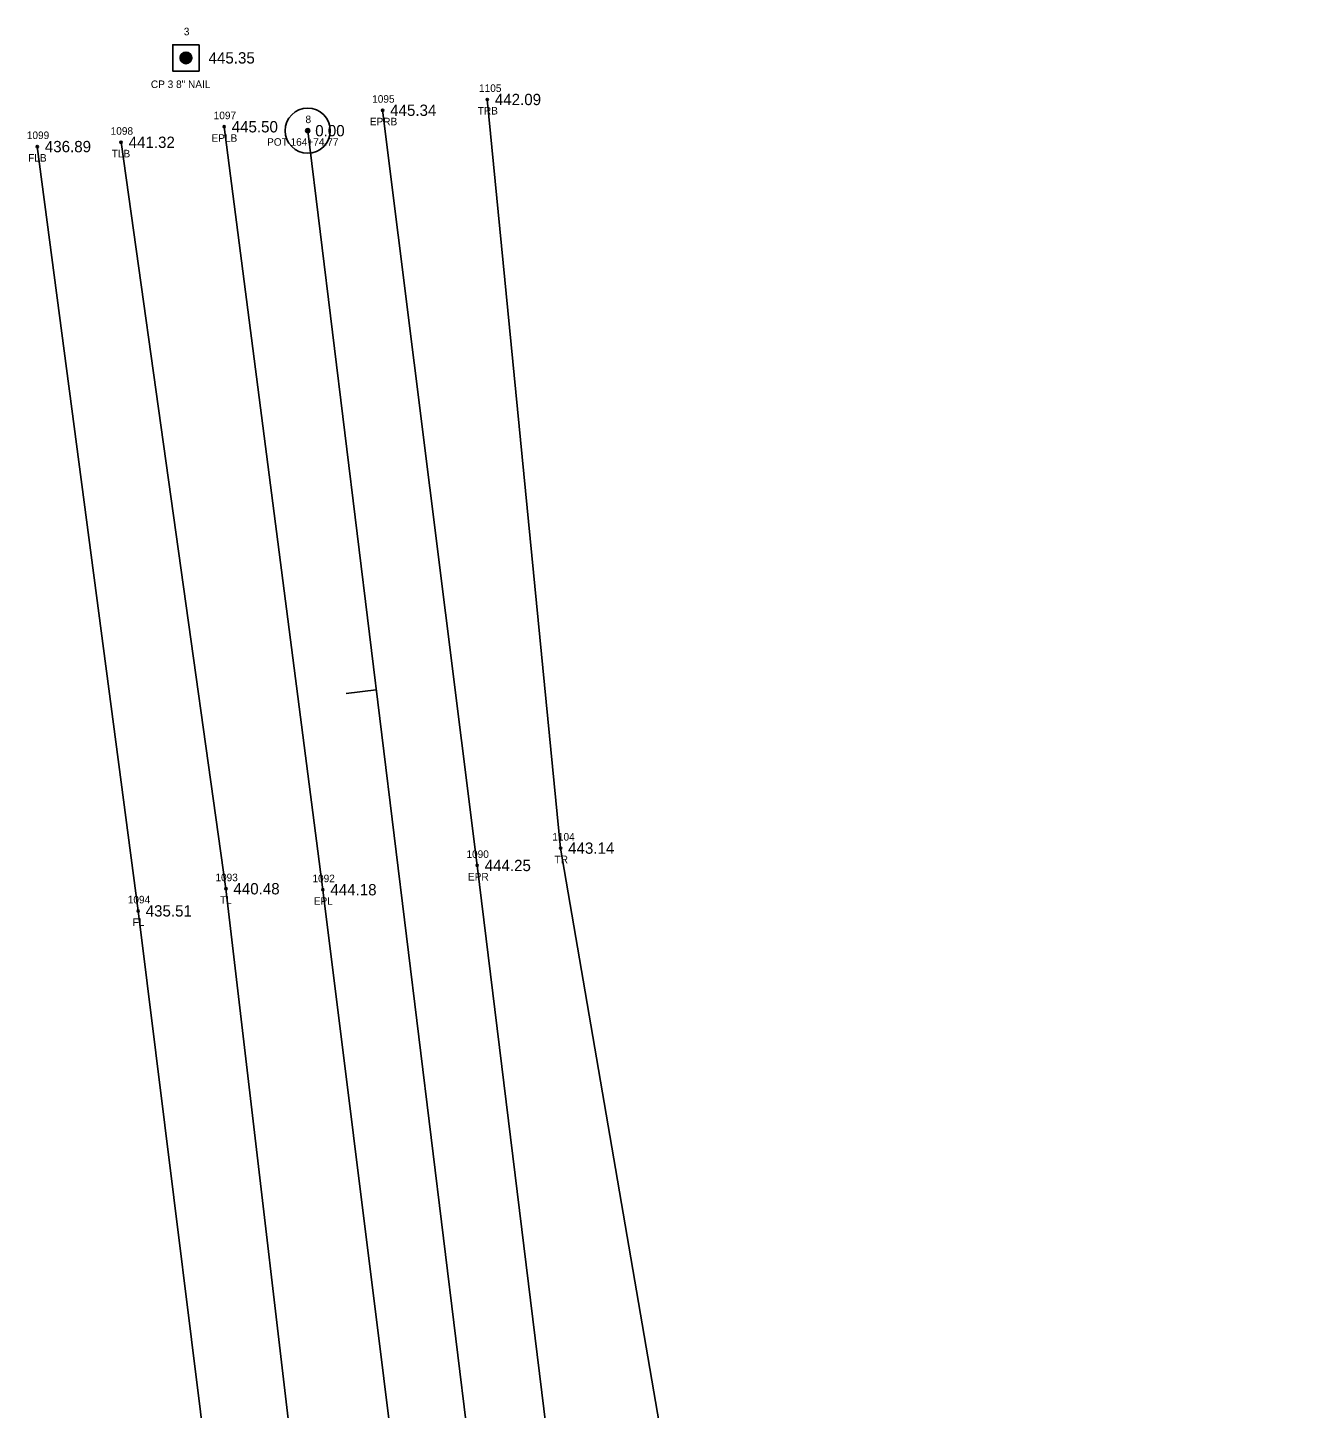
# Model space of a CAD drawing. Extents: x 1858454 to 1858924, y 1147053 to 1148170.
# Drawn here: x 1858580.5 to 1858751.6, y 1147986.7 to 1148169.9 of the extents above; entities that cross this region are included whole.
import ezdxf

# ---------------------------------------------------------------- set-up
doc = ezdxf.new("R2010")
doc.units = 0
for name, color, linetype in [('RD_EX_Fence_Other', 7, 'Continuous'), ('RD_EX_Fence_Other_txCode', 7, 'Continuous'), ('RD_EX_Road', 7, 'Continuous'), ('RD_EX_Road_txCode', 7, 'Continuous'), ('RD_EX_TX_Fence_Other_ELEV', 7, 'Continuous'), ('RD_EX_TX_Road_ELEV', 7, 'Continuous'), ('RD_EX_TX_VEG_ELEV', 7, 'Continuous'), ('RD_EX_VEG', 7, 'Continuous'), ('RD_EX_VEG_txCode', 7, 'Continuous'), ('RD_HC_Cl', 7, 'Continuous'), ('RD_HC_Data', 7, 'Continuous'), ('RD_HC_Data_Tic', 7, 'Continuous'), ('RD_HC_Survey', 7, 'Continuous'), ('RD_HC_Survey_ELEV', 7, 'Continuous'), ('RD_HC_Survey_txCode', 7, 'Continuous'), ('RD_HC_txCode', 7, 'Continuous'), ('RD_SMD_Locator', 7, 'Continuous')]:
    doc.layers.add(name, color=color, linetype=linetype)

msp = doc.modelspace()

# ---------------------------------------------------------------- linework, layer by layer
at = {"layer": 'RD_EX_Fence_Other'}
msp.add_lwpolyline([(1858628.27, 1147625.58), (1858627.01, 1147754.05), (1858615.95, 1147851.08), (1858606.98, 1147957.76), (1858595.17, 1148052.68), (1858581.78, 1148154.12)], dxfattribs=at)
at = {"layer": 'RD_EX_Road'}
for points in [[(1858679.02, 1147660.19), (1858688.73, 1147661.54), (1858677.21, 1147761.6), (1858664.75, 1147860.38), (1858652.33, 1147959.9), (1858640.18, 1148058.71), (1858627.63, 1148158.94)], [(1858679.02, 1147660.19), (1858669.49, 1147658.82), (1858657, 1147758.92), (1858643.96, 1147857.84), (1858631.87, 1147958), (1858619.69, 1148055.49), (1858606.59, 1148156.75)]]:
    msp.add_lwpolyline(points, dxfattribs=at)
at = {"layer": 'RD_EX_VEG'}
for points in [[(1858786.58, 1147073.62), (1858775.98, 1147174.64), (1858762.89, 1147274.03), (1858752.24, 1147373.24), (1858736.96, 1147479.89), (1858729.06, 1147571.9), (1858711.6, 1147670.3), (1858690.41, 1147764.38), (1858680.89, 1147862.43), (1858668.42, 1147961.01), (1858651.26, 1148061.01), (1858641.53, 1148160.37)], [(1858726.29, 1147071.02), (1858708.41, 1147166.41), (1858698.92, 1147264.27), (1858694.52, 1147368.74), (1858682.22, 1147467.57), (1858636.43, 1147636.58), (1858645.41, 1147757.54), (1858631.11, 1147856.08), (1858618.46, 1147956.68), (1858606.82, 1148055.62), (1858592.91, 1148154.69)]]:
    msp.add_lwpolyline(points, dxfattribs=at)
at = {"layer": 'RD_HC_Cl'}
msp.add_line((1858750.25, 1147074.55), (1858617.68, 1148156.23), dxfattribs=at)
at = {"layer": 'RD_HC_Data'}
for radius in [3, 0.282]:
    msp.add_circle((1858617.68, 1148156.23), radius, dxfattribs=at)
at = {"layer": 'RD_HC_Data_Tic'}
msp.add_line((1858626.77, 1148082.01), (1858622.8, 1148081.53), dxfattribs=at)
at = {"layer": 'RD_HC_Survey'}
for p, q in [((1858600.77, 1148165.71), (1858600.77, 1148166.07)), ((1858600.79, 1148165.63), (1858600.79, 1148166.15)), ((1858600.82, 1148165.57), (1858600.82, 1148166.21)), ((1858600.84, 1148165.52), (1858600.84, 1148166.26)), ((1858600.87, 1148165.48), (1858600.87, 1148166.3)), ((1858600.89, 1148165.44), (1858600.89, 1148166.34)), ((1858600.92, 1148165.41), (1858600.92, 1148166.37)), ((1858600.94, 1148165.38), (1858600.94, 1148166.4)), ((1858600.97, 1148165.35), (1858600.97, 1148166.43)), ((1858600.99, 1148165.33), (1858600.99, 1148166.45)), ((1858601.02, 1148165.31), (1858601.02, 1148166.48)), ((1858601.04, 1148165.29), (1858601.04, 1148166.5)), ((1858601.07, 1148165.27), (1858601.07, 1148166.52)), ((1858601.09, 1148165.25), (1858601.09, 1148166.53)), ((1858601.12, 1148165.24), (1858601.12, 1148166.55)), ((1858601.14, 1148165.22), (1858601.14, 1148166.56)), ((1858601.17, 1148165.21), (1858601.17, 1148166.58)), ((1858601.19, 1148165.2), (1858601.19, 1148166.59)), ((1858601.22, 1148165.18), (1858601.22, 1148166.6)), ((1858601.24, 1148165.17), (1858601.24, 1148166.61)), ((1858601.26, 1148165.17), (1858601.26, 1148166.62)), ((1858601.29, 1148165.16), (1858601.29, 1148166.63)), ((1858601.31, 1148165.15), (1858601.31, 1148166.63)), ((1858601.34, 1148165.14), (1858601.34, 1148166.64)), ((1858601.36, 1148165.14), (1858601.36, 1148166.65)), ((1858601.39, 1148165.13), (1858601.39, 1148166.65)), ((1858601.41, 1148165.13), (1858601.41, 1148166.65)), ((1858601.44, 1148165.13), (1858601.44, 1148166.66)), ((1858601.46, 1148165.12), (1858601.46, 1148166.66)), ((1858601.49, 1148165.12), (1858601.49, 1148166.66)), ((1858601.51, 1148165.12), (1858601.51, 1148166.66)), ((1858601.54, 1148165.12), (1858601.54, 1148166.66)), ((1858601.56, 1148165.12), (1858601.56, 1148166.66)), ((1858601.59, 1148165.13), (1858601.59, 1148166.66)), ((1858601.61, 1148165.13), (1858601.61, 1148166.66)), ((1858601.64, 1148165.13), (1858601.64, 1148166.65)), ((1858601.66, 1148165.14), (1858601.66, 1148166.65)), ((1858601.69, 1148165.14), (1858601.69, 1148166.64)), ((1858601.71, 1148165.15), (1858601.71, 1148166.64)), ((1858601.73, 1148165.15), (1858601.73, 1148166.63)), ((1858601.76, 1148165.16), (1858601.76, 1148166.62)), ((1858601.78, 1148165.17), (1858601.78, 1148166.61)), ((1858601.81, 1148165.18), (1858601.81, 1148166.6)), ((1858601.83, 1148165.19), (1858601.83, 1148166.59)), ((1858601.86, 1148165.2), (1858601.86, 1148166.58)), ((1858601.88, 1148165.21), (1858601.88, 1148166.57)), ((1858601.91, 1148165.23), (1858601.91, 1148166.56)), ((1858601.93, 1148165.24), (1858601.93, 1148166.54)), ((1858601.96, 1148165.26), (1858601.96, 1148166.52)), ((1858601.98, 1148165.28), (1858601.98, 1148166.51)), ((1858602.01, 1148165.3), (1858602.01, 1148166.49)), ((1858602.03, 1148165.32), (1858602.03, 1148166.46)), ((1858602.06, 1148165.34), (1858602.06, 1148166.44)), ((1858602.08, 1148165.37), (1858602.08, 1148166.42)), ((1858602.11, 1148165.4), (1858602.11, 1148166.39)), ((1858602.13, 1148165.43), (1858602.13, 1148166.36)), ((1858602.16, 1148165.46), (1858602.16, 1148166.32)), ((1858602.18, 1148165.5), (1858602.18, 1148166.28)), ((1858602.2, 1148165.55), (1858602.2, 1148166.24)), ((1858602.23, 1148165.6), (1858602.23, 1148166.18)), ((1858602.25, 1148165.67), (1858602.25, 1148166.11)), ((1858602.28, 1148165.78), (1858602.28, 1148166))]:
    msp.add_line(p, q, dxfattribs=at)
msp.add_lwpolyline([(1858603.27, 1148167.64), (1858599.77, 1148167.64), (1858599.77, 1148164.14), (1858603.27, 1148164.14)], close=True, dxfattribs=at)
msp.add_circle((1858601.52, 1148165.89), 0.769, dxfattribs=at)
at = {"layer": 'RD_SMD_Locator'}
for centre in [(1858601.52, 1148165.89), (1858641.53, 1148160.37), (1858627.63, 1148158.94), (1858606.59, 1148156.75), (1858592.91, 1148154.69), (1858617.68, 1148156.23), (1858581.78, 1148154.12), (1858651.26, 1148061.01), (1858640.18, 1148058.71), (1858606.82, 1148055.62), (1858619.69, 1148055.49), (1858595.17, 1148052.68)]:
    msp.add_circle(centre, 0.15, dxfattribs=at)

# ---------------------------------------------------------------- texts
at = {"layer": 'RD_EX_Fence_Other_txCode'}
for s, p in [('1099', (1858580.39, 1148155.12)), ('FLB', (1858580.57, 1148152.12)), ('1094', (1858593.79, 1148053.68)), ('FL', (1858594.44, 1148050.68))]:
    msp.add_text(s, height=1, dxfattribs=at).set_placement(p)
at = {"layer": 'RD_EX_Road_txCode'}
for s, p in [('1095', (1858626.24, 1148159.94)), ('1097', (1858605.2, 1148157.75)), ('EPRB', (1858625.93, 1148156.94)), ('EPLB', (1858604.91, 1148154.75)), ('1090', (1858638.76, 1148059.71)), ('EPR', (1858638.96, 1148056.71)), ('1092', (1858618.31, 1148056.49)), ('EPL', (1858618.49, 1148053.49))]:
    msp.add_text(s, height=1, dxfattribs=at).set_placement(p)
at = {"layer": 'RD_EX_TX_Fence_Other_ELEV'}
for s, p in [('436.89', (1858582.78, 1148153.37)), ('435.51', (1858596.17, 1148051.93))]:
    msp.add_text(s, height=1.5, dxfattribs=at).set_placement(p)
at = {"layer": 'RD_EX_TX_Road_ELEV'}
for s, p in [('445.34', (1858628.63, 1148158.19)), ('445.50', (1858607.59, 1148156)), ('444.25', (1858641.18, 1148057.96)), ('444.18', (1858620.69, 1148054.74))]:
    msp.add_text(s, height=1.5, dxfattribs=at).set_placement(p)
at = {"layer": 'RD_EX_TX_VEG_ELEV'}
for s, p in [('442.09', (1858642.53, 1148159.62)), ('441.32', (1858593.91, 1148153.94)), ('443.14', (1858652.26, 1148060.26)), ('440.48', (1858607.82, 1148054.87))]:
    msp.add_text(s, height=1.5, dxfattribs=at).set_placement(p)
at = {"layer": 'RD_EX_VEG_txCode'}
for s, p in [('1105', (1858640.43, 1148161.37)), ('TRB', (1858640.26, 1148158.37)), ('1098', (1858591.52, 1148155.69)), ('TLB', (1858591.66, 1148152.69)), ('1104', (1858650.16, 1148062.01)), ('TR', (1858650.46, 1148059.01)), ('1093', (1858605.43, 1148056.62)), ('TL', (1858606.04, 1148053.62))]:
    msp.add_text(s, height=1, dxfattribs=at).set_placement(p)
at = {"layer": 'RD_HC_Survey_ELEV'}
for s, p in [('445.35', (1858604.52, 1148165.14)), ('0.00', (1858618.68, 1148155.48))]:
    msp.add_text(s, height=1.5, dxfattribs=at).set_placement(p)
at = {"layer": 'RD_HC_Survey_txCode'}
for s, p in [('3', (1858601.23, 1148168.89)), ('CP 3 8" NAIL', (1858596.86, 1148161.89))]:
    msp.add_text(s, height=1, dxfattribs=at).set_placement(p)
at = {"layer": 'RD_HC_txCode'}
for s, p in [('8', (1858617.39, 1148157.23)), ('POT 164+74.77', (1858612.29, 1148154.23))]:
    msp.add_text(s, height=1, dxfattribs=at).set_placement(p)

doc.saveas('drawing.dxf')
